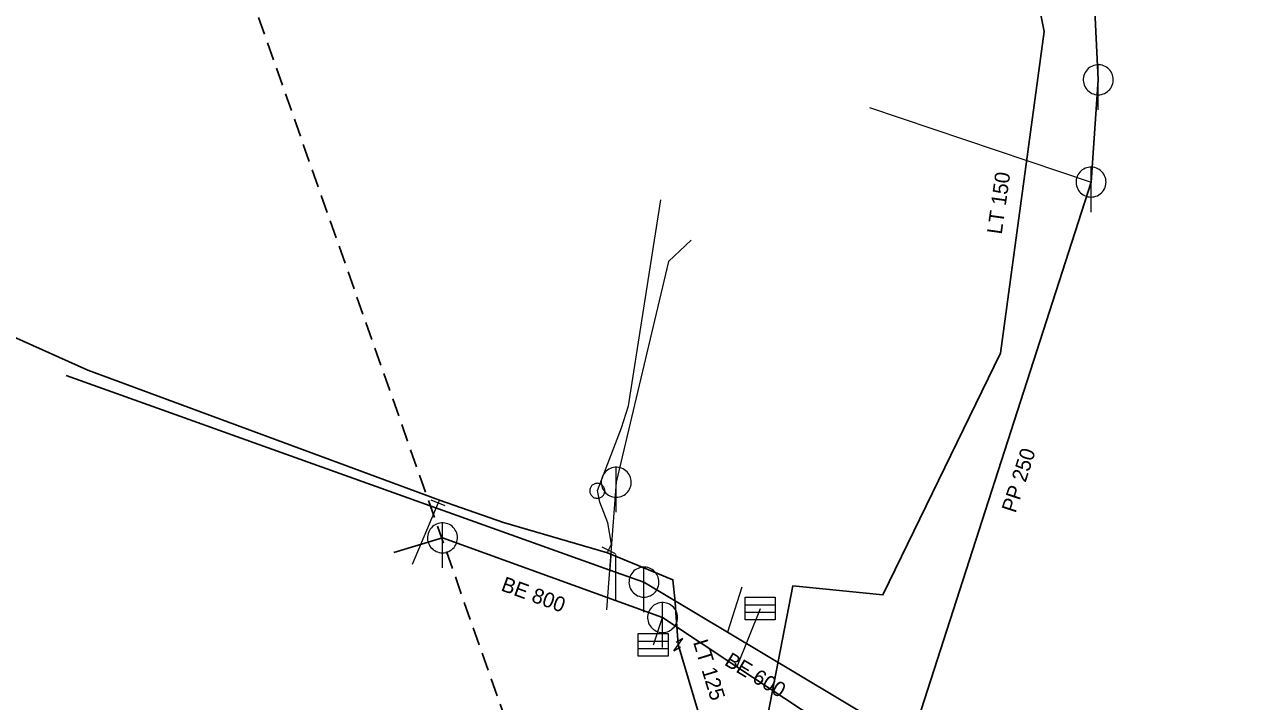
# Model space of a CAD drawing. Extents: x -659250 to -657316, y -997555 to -993684.
# Drawn here: x -658756.5 to -658675.1, y -994971 to -994925.7 of the extents above; entities that cross this region are included whole.
import ezdxf

# ---------------------------------------------------------------- set-up
doc = ezdxf.new("R2010")
doc.units = 0
doc.header["$LTSCALE"] = 0.4
doc.linetypes.add('MEDIUM_DASHED', pattern=[4.5, 3, -1.5])
doc.layers.add('1', color=7, linetype='Continuous')
for name, color, linetype, lineweight in [('11', 7, 'Continuous', 13), ('13', 7, 'Continuous', 13), ('14', 7, 'Continuous', 25), ('17', 7, 'Continuous', 25), ('22', 7, 'Continuous', 13), ('23', 7, 'Continuous', 13), ('34', 7, 'Continuous', 13), ('47', 7, 'Continuous', 13), ('63', 7, 'MEDIUM_DASHED', 25)]:
    doc.layers.add(name, color=color, linetype=linetype, lineweight=lineweight)

msp = doc.modelspace()

# ---------------------------------------------------------------- linework, layer by layer
at = {"layer": '11'}
for p, q in [((-658700.09, -994931.309), (-658685.32, -994936.28)), ((-658717.34, -994961.21), (-658717.412, -994962.175)), ((-658717.03, -994961.14), (-658717.039, -994964.21)), ((-658708.609, -994963.329), (-658709.57, -994966.329)), ((-658707.379, -994964.76), (-658708.94, -994968.64)), ((-658714.51, -994967.18), (-658713.899, -994965.35))]:
    msp.add_line(p, q, dxfattribs=at)
for points in [[(-658712, -994940.149), (-658713.5, -994941.59), (-658716.989, -994956.32)], [(-658716.989, -994956.32), (-658717.48, -994962.77), (-658717.649, -994964.829)]]:
    msp.add_lwpolyline(points, dxfattribs=at)
at = {"layer": '13'}
for p, q in [((-658728.867, -994957.704), (-658730.6, -994961.82)), ((-658717.512, -994960.853), (-658717.305, -994960.454))]:
    msp.add_line(p, q, dxfattribs=at)
for points in [[(-658718.23, -994956.87), (-658716.629, -994952.68), (-658716.162, -994951.209), (-658714.02, -994937.469)], [(-658717.305, -994960.454), (-658717.559, -994959.039), (-658718.09, -994957.66), (-658718.23, -994956.87)]]:
    msp.add_lwpolyline(points, dxfattribs=at)
at = {"layer": '14'}
for p, q in [((-658685.25, -994920.92), (-658684.84, -994929.449)), ((-658684.84, -994929.449), (-658685.32, -994936.28)), ((-658685.32, -994936.28), (-658697.34, -994973.64)), ((-658731.829, -994961.02), (-658728.579, -994960.03))]:
    msp.add_line(p, q, dxfattribs=at)
at = {"layer": '14', "lineweight": 13}
for p, q in [((-658728.789, -994957.52), (-658728.867, -994957.704)), ((-658717.583, -994961.04), (-658717.512, -994960.853))]:
    msp.add_line(p, q, dxfattribs=at)
at = {"layer": '14'}
for points in [[(-658753.69, -994949.19), (-658745.789, -994952.02), (-658742.32, -994953.26), (-658717.41, -994962.18), (-658715.14, -994962.989)], [(-658728.579, -994960.03), (-658717.039, -994964.21), (-658713.899, -994965.35)], [(-658715.14, -994962.989), (-658709.57, -994966.329), (-658697.34, -994973.64)], [(-658713.899, -994965.35), (-658708.94, -994968.64), (-658701.44, -994973.609)]]:
    msp.add_lwpolyline(points, dxfattribs=at)
at = {"layer": '17'}
for points in [[(-658689.166, -994922.67), (-658688.447, -994926.223), (-658691.355, -994947.704), (-658699.204, -994963.84), (-658705.204, -994963.234), (-658707.419, -994974.603)], [(-658779.64, -994934.399), (-658777.78, -994935.51), (-658764.84, -994942.53), (-658758.079, -994946.19), (-658757.879, -994946.289), (-658757.202, -994946.605), (-658752.244, -994948.841), (-658728.789, -994957.52), (-658724.51, -994959.01), (-658717.583, -994961.04), (-658713.21, -994962.829), (-658713.059, -994964.309), (-658713.006, -994965.042), (-658712.853, -994967.16)], [(-658708.5, -994974.644), (-658709.373, -994974.399), (-658711.07, -994973.143), (-658712.853, -994967.16)]]:
    msp.add_lwpolyline(points, dxfattribs=at)
at = {"layer": '22'}
for p, q in [((-658684.84, -994931.45), (-658684.839, -994928.45)), ((-658685.32, -994938.28), (-658685.319, -994935.28)), ((-658716.989, -994958.32), (-658716.988, -994955.32)), ((-658728.579, -994962.03), (-658728.578, -994959.03)), ((-658715.14, -994964.989), (-658715.139, -994961.989)), ((-658713.899, -994967.35), (-658713.898, -994964.35)), ((-658708.39, -994964.503), (-658706.39, -994964.503)), ((-658708.39, -994965.003), (-658706.39, -994965.003)), ((-658715.521, -994966.923), (-658713.521, -994966.923)), ((-658715.521, -994967.423), (-658713.521, -994967.423))]:
    msp.add_line(p, q, dxfattribs=at)
for points in [[(-658683.84, -994929.45), (-658683.845, -994929.341), (-658683.863, -994929.233), (-658683.893, -994929.127), (-658683.933, -994929.026), (-658683.985, -994928.929), (-658684.047, -994928.839), (-658684.119, -994928.756), (-658684.199, -994928.682), (-658684.287, -994928.616), (-658684.381, -994928.561), (-658684.481, -994928.516), (-658684.586, -994928.483), (-658684.693, -994928.461), (-658684.802, -994928.451), (-658684.912, -994928.453), (-658685.02, -994928.467), (-658685.127, -994928.492), (-658685.23, -994928.529), (-658685.328, -994928.578), (-658685.42, -994928.636), (-658685.506, -994928.705), (-658685.583, -994928.782), (-658685.652, -994928.868), (-658685.711, -994928.96), (-658685.759, -994929.058), (-658685.796, -994929.161), (-658685.822, -994929.268), (-658685.836, -994929.376), (-658685.839, -994929.486), (-658685.829, -994929.595), (-658685.808, -994929.702), (-658685.774, -994929.806), (-658685.73, -994929.906), (-658685.675, -994930.001), (-658685.609, -994930.089), (-658685.535, -994930.169), (-658685.452, -994930.241), (-658685.362, -994930.303), (-658685.266, -994930.355), (-658685.164, -994930.396), (-658685.059, -994930.426), (-658684.951, -994930.444), (-658684.841, -994930.45), (-658684.732, -994930.444), (-658684.624, -994930.426), (-658684.519, -994930.397), (-658684.417, -994930.356), (-658684.32, -994930.304), (-658684.23, -994930.242), (-658684.147, -994930.171), (-658684.072, -994930.091), (-658684.007, -994930.003), (-658683.951, -994929.909), (-658683.907, -994929.809), (-658683.873, -994929.705), (-658683.851, -994929.597), (-658683.841, -994929.488)], [(-658684.32, -994936.28), (-658684.325, -994936.171), (-658684.343, -994936.063), (-658684.373, -994935.957), (-658684.413, -994935.856), (-658684.465, -994935.759), (-658684.527, -994935.669), (-658684.599, -994935.586), (-658684.679, -994935.512), (-658684.767, -994935.446), (-658684.861, -994935.391), (-658684.961, -994935.346), (-658685.066, -994935.313), (-658685.173, -994935.291), (-658685.282, -994935.281), (-658685.392, -994935.283), (-658685.5, -994935.297), (-658685.607, -994935.322), (-658685.71, -994935.359), (-658685.808, -994935.408), (-658685.9, -994935.466), (-658685.986, -994935.535), (-658686.063, -994935.612), (-658686.132, -994935.698), (-658686.191, -994935.79), (-658686.239, -994935.888), (-658686.276, -994935.991), (-658686.302, -994936.098), (-658686.316, -994936.206), (-658686.319, -994936.316), (-658686.309, -994936.425), (-658686.288, -994936.532), (-658686.254, -994936.636), (-658686.21, -994936.736), (-658686.155, -994936.831), (-658686.089, -994936.919), (-658686.015, -994936.999), (-658685.932, -994937.071), (-658685.842, -994937.133), (-658685.746, -994937.185), (-658685.644, -994937.226), (-658685.539, -994937.256), (-658685.431, -994937.274), (-658685.321, -994937.28), (-658685.212, -994937.274), (-658685.104, -994937.256), (-658684.999, -994937.227), (-658684.897, -994937.186), (-658684.8, -994937.134), (-658684.71, -994937.072), (-658684.627, -994937.001), (-658684.552, -994936.921), (-658684.487, -994936.833), (-658684.431, -994936.739), (-658684.387, -994936.639), (-658684.353, -994936.535), (-658684.331, -994936.427), (-658684.321, -994936.318)], [(-658715.989, -994956.32), (-658715.994, -994956.211), (-658716.012, -994956.103), (-658716.042, -994955.997), (-658716.082, -994955.896), (-658716.134, -994955.799), (-658716.196, -994955.709), (-658716.268, -994955.626), (-658716.348, -994955.552), (-658716.436, -994955.486), (-658716.53, -994955.431), (-658716.63, -994955.386), (-658716.735, -994955.353), (-658716.842, -994955.331), (-658716.951, -994955.321), (-658717.061, -994955.323), (-658717.169, -994955.337), (-658717.276, -994955.362), (-658717.379, -994955.399), (-658717.477, -994955.448), (-658717.569, -994955.506), (-658717.655, -994955.575), (-658717.732, -994955.652), (-658717.801, -994955.738), (-658717.86, -994955.83), (-658717.908, -994955.928), (-658717.945, -994956.031), (-658717.971, -994956.138), (-658717.985, -994956.246), (-658717.988, -994956.356), (-658717.978, -994956.465), (-658717.957, -994956.572), (-658717.923, -994956.676), (-658717.879, -994956.776), (-658717.824, -994956.871), (-658717.758, -994956.959), (-658717.684, -994957.039), (-658717.601, -994957.111), (-658717.511, -994957.173), (-658717.415, -994957.225), (-658717.313, -994957.266), (-658717.208, -994957.296), (-658717.1, -994957.314), (-658716.99, -994957.32), (-658716.881, -994957.314), (-658716.773, -994957.296), (-658716.668, -994957.267), (-658716.566, -994957.226), (-658716.469, -994957.174), (-658716.379, -994957.112), (-658716.296, -994957.041), (-658716.221, -994956.961), (-658716.156, -994956.873), (-658716.1, -994956.779), (-658716.056, -994956.679), (-658716.022, -994956.575), (-658716, -994956.467), (-658715.99, -994956.358)], [(-658727.579, -994960.03), (-658727.584, -994959.921), (-658727.602, -994959.813), (-658727.632, -994959.707), (-658727.672, -994959.606), (-658727.724, -994959.509), (-658727.786, -994959.419), (-658727.858, -994959.336), (-658727.938, -994959.262), (-658728.026, -994959.196), (-658728.12, -994959.141), (-658728.22, -994959.096), (-658728.325, -994959.063), (-658728.432, -994959.041), (-658728.541, -994959.031), (-658728.651, -994959.033), (-658728.759, -994959.047), (-658728.866, -994959.072), (-658728.969, -994959.109), (-658729.067, -994959.158), (-658729.159, -994959.216), (-658729.245, -994959.285), (-658729.322, -994959.362), (-658729.391, -994959.448), (-658729.45, -994959.54), (-658729.498, -994959.638), (-658729.535, -994959.741), (-658729.561, -994959.848), (-658729.575, -994959.956), (-658729.578, -994960.066), (-658729.568, -994960.175), (-658729.547, -994960.282), (-658729.513, -994960.386), (-658729.469, -994960.486), (-658729.414, -994960.581), (-658729.348, -994960.669), (-658729.274, -994960.749), (-658729.191, -994960.821), (-658729.101, -994960.883), (-658729.005, -994960.935), (-658728.903, -994960.976), (-658728.798, -994961.006), (-658728.69, -994961.024), (-658728.58, -994961.03), (-658728.471, -994961.024), (-658728.363, -994961.006), (-658728.258, -994960.977), (-658728.156, -994960.936), (-658728.059, -994960.884), (-658727.969, -994960.822), (-658727.886, -994960.751), (-658727.811, -994960.671), (-658727.746, -994960.583), (-658727.69, -994960.489), (-658727.646, -994960.389), (-658727.612, -994960.285), (-658727.59, -994960.177), (-658727.58, -994960.068)], [(-658714.14, -994962.989), (-658714.145, -994962.88), (-658714.163, -994962.772), (-658714.193, -994962.666), (-658714.233, -994962.565), (-658714.285, -994962.468), (-658714.347, -994962.378), (-658714.419, -994962.295), (-658714.499, -994962.221), (-658714.587, -994962.155), (-658714.681, -994962.1), (-658714.781, -994962.055), (-658714.886, -994962.022), (-658714.993, -994962), (-658715.102, -994961.99), (-658715.212, -994961.992), (-658715.32, -994962.006), (-658715.427, -994962.031), (-658715.53, -994962.068), (-658715.628, -994962.117), (-658715.72, -994962.175), (-658715.806, -994962.244), (-658715.883, -994962.321), (-658715.952, -994962.407), (-658716.011, -994962.499), (-658716.059, -994962.597), (-658716.096, -994962.7), (-658716.122, -994962.807), (-658716.136, -994962.915), (-658716.139, -994963.025), (-658716.129, -994963.134), (-658716.108, -994963.241), (-658716.074, -994963.345), (-658716.03, -994963.445), (-658715.975, -994963.54), (-658715.909, -994963.628), (-658715.835, -994963.708), (-658715.752, -994963.78), (-658715.662, -994963.842), (-658715.566, -994963.894), (-658715.464, -994963.935), (-658715.359, -994963.965), (-658715.251, -994963.983), (-658715.141, -994963.989), (-658715.032, -994963.983), (-658714.924, -994963.965), (-658714.819, -994963.936), (-658714.717, -994963.895), (-658714.62, -994963.843), (-658714.53, -994963.781), (-658714.447, -994963.71), (-658714.372, -994963.63), (-658714.307, -994963.542), (-658714.251, -994963.448), (-658714.207, -994963.348), (-658714.173, -994963.244), (-658714.151, -994963.136), (-658714.141, -994963.027)], [(-658708.39, -994964.003), (-658706.39, -994964.003), (-658706.39, -994965.503), (-658708.39, -994965.503)], [(-658712.899, -994965.35), (-658712.904, -994965.241), (-658712.922, -994965.133), (-658712.952, -994965.027), (-658712.992, -994964.926), (-658713.044, -994964.829), (-658713.106, -994964.739), (-658713.178, -994964.656), (-658713.258, -994964.582), (-658713.346, -994964.516), (-658713.44, -994964.461), (-658713.54, -994964.416), (-658713.645, -994964.383), (-658713.752, -994964.361), (-658713.861, -994964.351), (-658713.971, -994964.353), (-658714.079, -994964.367), (-658714.186, -994964.392), (-658714.289, -994964.429), (-658714.387, -994964.478), (-658714.479, -994964.536), (-658714.565, -994964.605), (-658714.642, -994964.682), (-658714.711, -994964.768), (-658714.77, -994964.86), (-658714.818, -994964.958), (-658714.855, -994965.061), (-658714.881, -994965.168), (-658714.895, -994965.276), (-658714.898, -994965.386), (-658714.888, -994965.495), (-658714.867, -994965.602), (-658714.833, -994965.706), (-658714.789, -994965.806), (-658714.734, -994965.901), (-658714.668, -994965.989), (-658714.594, -994966.069), (-658714.511, -994966.141), (-658714.421, -994966.203), (-658714.325, -994966.255), (-658714.223, -994966.296), (-658714.118, -994966.326), (-658714.01, -994966.344), (-658713.9, -994966.35), (-658713.791, -994966.344), (-658713.683, -994966.326), (-658713.578, -994966.297), (-658713.476, -994966.256), (-658713.379, -994966.204), (-658713.289, -994966.142), (-658713.206, -994966.071), (-658713.131, -994965.991), (-658713.066, -994965.903), (-658713.01, -994965.809), (-658712.966, -994965.709), (-658712.932, -994965.605), (-658712.91, -994965.497), (-658712.9, -994965.388)], [(-658715.521, -994966.423), (-658713.521, -994966.423), (-658713.521, -994967.923), (-658715.521, -994967.923)]]:
    msp.add_lwpolyline(points, close=True, dxfattribs=at)
at = {"layer": '23'}
for points in [[(-658717.753, -994956.887), (-658717.755, -994956.834), (-658717.765, -994956.782), (-658717.78, -994956.733), (-658717.799, -994956.684), (-658717.823, -994956.638), (-658717.853, -994956.594), (-658717.886, -994956.554), (-658717.923, -994956.518), (-658717.964, -994956.485), (-658718.008, -994956.457), (-658718.054, -994956.433), (-658718.105, -994956.415), (-658718.155, -994956.402), (-658718.206, -994956.395), (-658718.258, -994956.392), (-658718.312, -994956.396), (-658718.362, -994956.404), (-658718.414, -994956.419), (-658718.461, -994956.437), (-658718.508, -994956.461), (-658718.552, -994956.492), (-658718.592, -994956.525), (-658718.629, -994956.563), (-658718.662, -994956.603), (-658718.689, -994956.647), (-658718.712, -994956.695), (-658718.73, -994956.743), (-658718.743, -994956.794), (-658718.75, -994956.846), (-658718.753, -994956.898), (-658718.75, -994956.95), (-658718.741, -994957.002), (-658718.727, -994957.053), (-658718.708, -994957.101), (-658718.683, -994957.146), (-658718.654, -994957.19), (-658718.62, -994957.231), (-658718.583, -994957.268), (-658718.542, -994957.3)], [(-658718.414, -994956.419), (-658718.461, -994956.437), (-658718.508, -994956.461), (-658718.552, -994956.492), (-658718.592, -994956.525), (-658718.629, -994956.563), (-658718.662, -994956.603), (-658718.689, -994956.647), (-658718.712, -994956.695), (-658718.73, -994956.743), (-658718.743, -994956.794), (-658718.75, -994956.846), (-658718.753, -994956.898), (-658718.75, -994956.95), (-658718.741, -994957.002), (-658718.727, -994957.053), (-658718.708, -994957.101), (-658718.683, -994957.146), (-658718.654, -994957.19), (-658718.62, -994957.231), (-658718.583, -994957.268), (-658718.542, -994957.3), (-658718.499, -994957.328), (-658718.451, -994957.351), (-658718.402, -994957.37), (-658718.351, -994957.382), (-658718.299, -994957.389), (-658718.248, -994957.392), (-658718.196, -994957.388), (-658718.144, -994957.38), (-658718.093, -994957.366), (-658718.044, -994957.346), (-658717.998, -994957.322), (-658717.955, -994957.294), (-658717.915, -994957.259), (-658717.878, -994957.223), (-658717.846, -994957.182), (-658717.817, -994957.137), (-658717.794, -994957.09), (-658717.776, -994957.041)], [(-658718.542, -994957.3), (-658718.499, -994957.328), (-658718.451, -994957.351), (-658718.402, -994957.37), (-658718.351, -994957.382), (-658718.299, -994957.389), (-658718.248, -994957.392), (-658718.196, -994957.388), (-658718.144, -994957.38), (-658718.093, -994957.366), (-658718.044, -994957.346), (-658717.998, -994957.322), (-658717.955, -994957.294), (-658717.915, -994957.259), (-658717.878, -994957.223), (-658717.846, -994957.182), (-658717.817, -994957.137), (-658717.794, -994957.09), (-658717.776, -994957.041), (-658717.764, -994956.99), (-658717.755, -994956.939), (-658717.753, -994956.887), (-658717.755, -994956.834), (-658717.765, -994956.782), (-658717.78, -994956.733), (-658717.799, -994956.684), (-658717.823, -994956.638), (-658717.853, -994956.594), (-658717.886, -994956.554), (-658717.923, -994956.518), (-658717.964, -994956.485), (-658718.008, -994956.457), (-658718.054, -994956.433), (-658718.105, -994956.415), (-658718.155, -994956.402), (-658718.206, -994956.395), (-658718.258, -994956.392), (-658718.312, -994956.396), (-658718.362, -994956.404), (-658718.414, -994956.419)], [(-658717.776, -994957.041), (-658717.764, -994956.99), (-658717.755, -994956.939), (-658717.753, -994956.887)]]:
    msp.add_lwpolyline(points, dxfattribs=at)
at = {"layer": '34'}
for p, q in [((-658728.405, -994957.897), (-658729.327, -994957.509)), ((-658717.955, -994960.622), (-658717.068, -994961.083))]:
    msp.add_line(p, q, dxfattribs=at)
at = {"layer": '47'}
msp.add_line((-658713.147, -994967.575), (-658712.714, -994967.305), dxfattribs=at)
msp.add_lwpolyline([(-658713.147, -994967.575), (-658712.558, -994966.744), (-658712.991, -994967.014)], dxfattribs=at)
at = {"layer": '63'}
msp.add_lwpolyline([(-659116.685, -993855.266), (-658551.464, -993848.288), (-658551.464, -993848.288), (-657316.352, -997490.822), (-657316.352, -997490.822), (-657839.705, -997490.822), (-657839.705, -997490.822)], close=True, dxfattribs=at)

# ---------------------------------------------------------------- texts
at = {"layer": '1'}
for s, rotation, p in [('LT 150', 82, (-658691.278, -994939.804)), ('PP 250', 72, (-658690.358, -994958.422)), ('BE 800', 340, (-658724.736, -994963.533)), ('LT 125', 287, (-658711.873, -994966.995)), ('BE 600', 329, (-658709.836, -994968.483))]:
    msp.add_text(s, height=1, rotation=rotation, dxfattribs=at).set_placement(p)

doc.saveas('drawing.dxf')
